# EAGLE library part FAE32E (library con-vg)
CONNECTOR femlae 32 pins, type E, rows AC, grid 5.08 mm
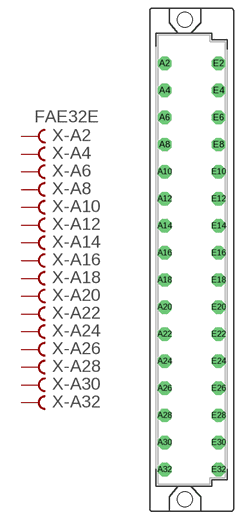
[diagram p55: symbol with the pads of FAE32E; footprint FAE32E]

Designator prefix X; gates -A2=FVAL -A4=FEM -A6=FEM -A8=FEM -A10=FEM -A12=FEM -A14=FEM -A16=FEM -A18=FEM -A20=FEM -A22=FEM -A24=FEM -A26=FEM -A28=FEM -A30=FEM -A32=FEM -E2=FVAL -E4=FEM -E6=FEM -E8=FEM -E10=FEM -E12=FEM -E14=FEM -E16=FEM -E18=FEM -E20=FEM -E22=FEM -E24=FEM -E26=FEM -E28=FEM -E30=FEM -E32=FEM

## FAE32E  [FAE32E]
A2  -A2:B  pas
A4  -A4:B  pas
A6  -A6:B  pas
A8  -A8:B  pas
A10  -A10:B  pas
A12  -A12:B  pas
A14  -A14:B  pas
A16  -A16:B  pas
A18  -A18:B  pas
A20  -A20:B  pas
A22  -A22:B  pas
A24  -A24:B  pas
A26  -A26:B  pas
A28  -A28:B  pas
A30  -A30:B  pas
A32  -A32:B  pas
E2  -E2:B  pas
E4  -E4:B  pas
E6  -E6:B  pas
E8  -E8:B  pas
E10  -E10:B  pas
E12  -E12:B  pas
E14  -E14:B  pas
E16  -E16:B  pas
E18  -E18:B  pas
E20  -E20:B  pas
E22  -E22:B  pas
E24  -E24:B  pas
E26  -E26:B  pas
E28  -E28:B  pas
E30  -E30:B  pas
E32  -E32:B  pas

## Footprint FAE32E (pad centres in mm)
CONNECTOR female 32 pins, type E, rows AC, grid 5.08 mm
drill 1.676 octagon: A2 -5.08,36.83; A4 -5.08,31.75; A6 -5.08,26.67; A8 -5.08,21.59; A10 -5.08,16.51; A12 -5.08,11.43; A14 -5.08,6.35; A16 -5.08,1.27; A18 -5.08,-3.81; A20 -5.08,-8.89; A22 -5.08,-13.97; A24 -5.08,-19.05; A26 -5.08,-24.13; A28 -5.08,-29.21; A30 -5.08,-34.29; A32 -5.08,-39.37; E2 5.08,36.83; E4 5.08,31.75; E6 5.08,26.67; E8 5.08,21.59; E10 5.08,16.51; E12 5.08,11.43; E14 5.08,6.35; E16 5.08,1.27; E18 5.08,-3.81; E20 5.08,-8.89; E22 5.08,-13.97; E24 5.08,-19.05; E26 5.08,-24.13; E28 5.08,-29.21; E30 5.08,-34.29; E32 5.08,-39.37
hole 2.794 at -1.27,44.983
hole 2.794 at -1.27,-44.983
